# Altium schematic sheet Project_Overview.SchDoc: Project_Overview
size A4; Date: Not used; ApprovedBy: Not used; CheckedBy: Not used; Author: Not used; CompanyName: STMicroelectronics; DrawnBy: Not used; Engineer: Not used; Organization: Not used; Address1: Not used; Address2: Not used; Address3: Not used; Address4: Not used; DocumentNumber: Not used; Revision: Not used; SheetNumber: 1; SheetTotal: 16
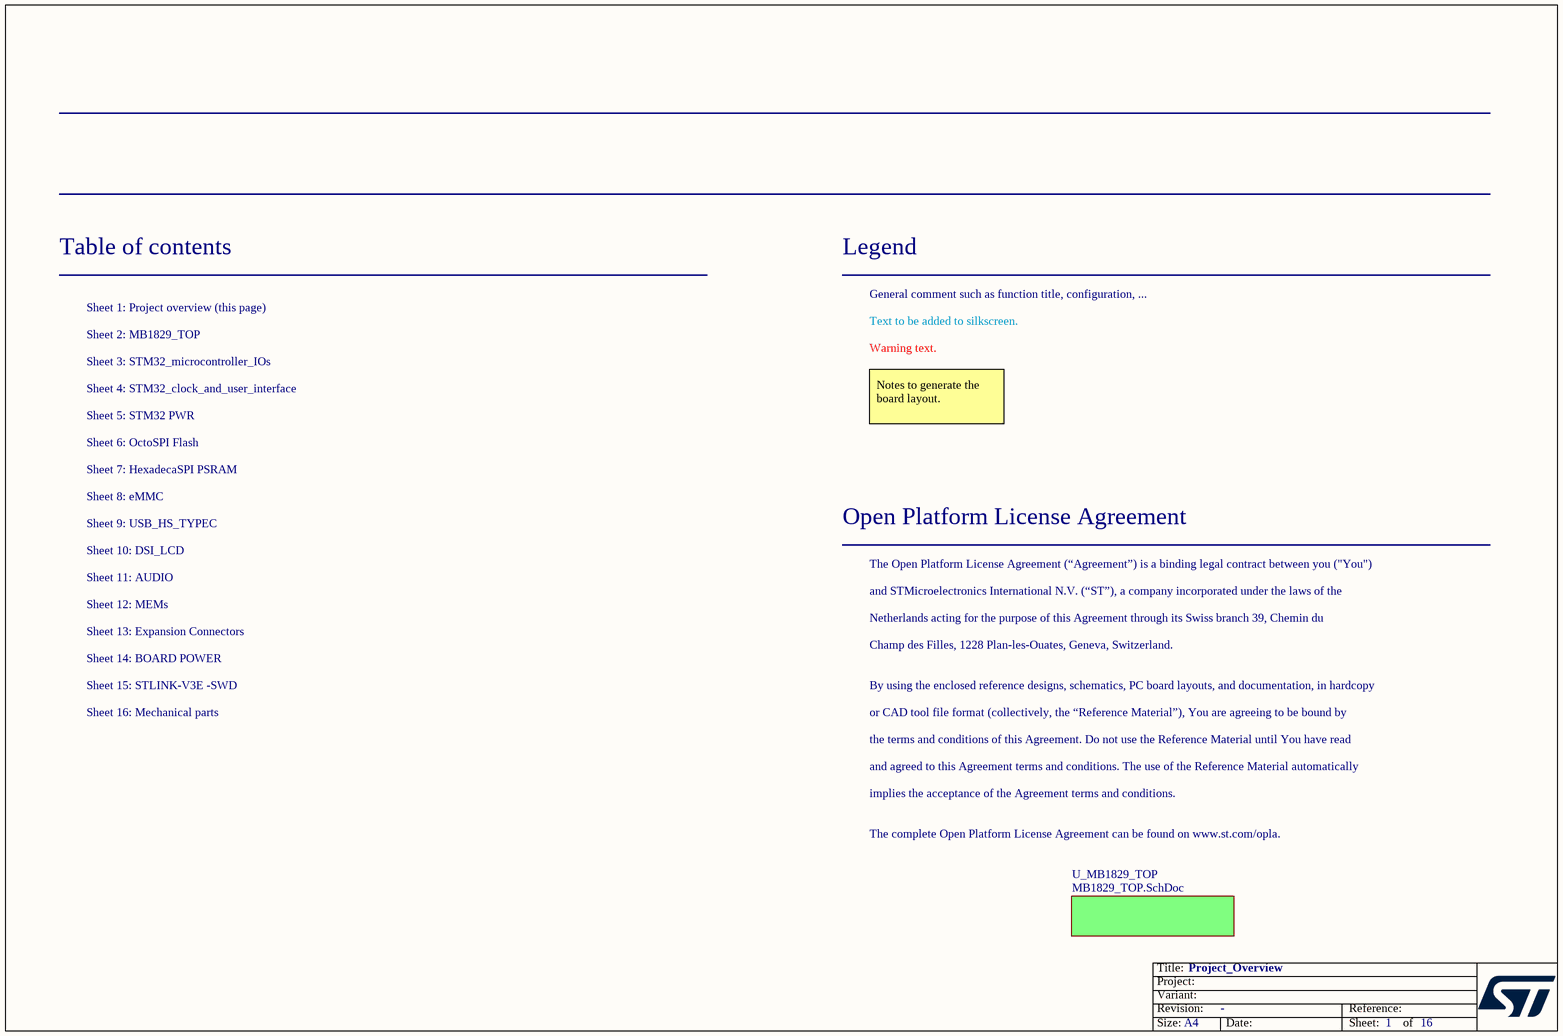
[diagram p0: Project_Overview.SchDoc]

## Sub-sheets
U_MB1829_TOP = MB1829_TOP.SchDoc: no entries

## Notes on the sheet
- Table of contents
- Sheet 1: Project overview (this page)
- Legend
- General comment such as function title, configuration, ...
- Sheet 2: MB1829_TOP
- Sheet 3: STM32_microcontroller_IOs
- Text to be added to silkscreen.
- Warning text.
- Sheet 4: STM32_clock_and_user_interface
- Sheet 6: OctoSPI Flash
- Sheet 5: STM32 PWR
- Notes to generate the board layout.
- Sheet 8: eMMC
- Sheet 7: HexadecaSPI PSRAM
- Sheet 10: DSI_LCD
- Sheet 11: AUDIO
- Sheet 9: USB_HS_TYPEC
- Open Platform License Agreement
- The Open Platform License Agreement (“Agreement”) is a binding legal contract between you ("You")
- Sheet 13: Expansion Connectors
- Sheet 12: MEMs
- and STMicroelectronics International N.V. (“ST”), a company incorporated under the laws of the
- Netherlands acting for the purpose of this Agreement through its Swiss branch 39, Chemin du
- Champ des Filles, 1228 Plan-les-Ouates, Geneva, Switzerland.
- Sheet 15: STLINK-V3E -SWD
- Sheet 16: Mechanical parts
- Sheet 14: BOARD POWER
- By using the enclosed reference designs, schematics, PC board layouts, and documentation, in hardcopy
- or CAD tool file format (collectively, the “Reference Material”), You are agreeing to be bound by
- the terms and conditions of this Agreement. Do not use the Reference Material until You have read
- and agreed to this Agreement terms and conditions. The use of the Reference Material automatically
- implies the acceptance of the Agreement terms and conditions.
- The complete Open Platform License Agreement can be found on www.st.com/opla.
